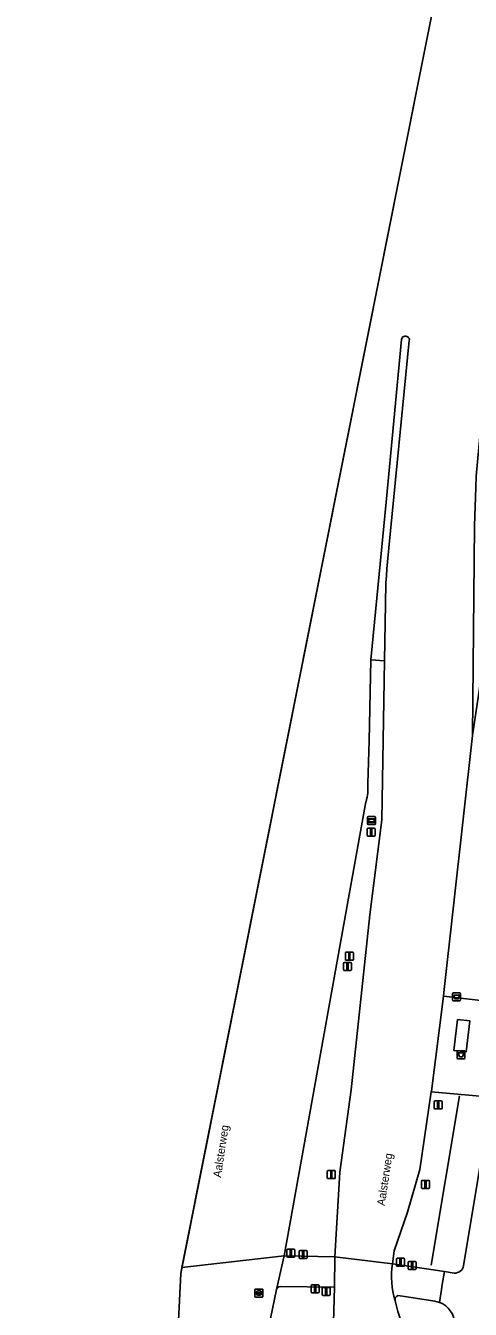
# Model space of a CAD drawing. Extents: x 161483 to 162250, y 379484 to 380833.
# Drawn here: x 161483 to 161538.6, y 379648 to 379808.4 of the extents above; entities that cross this region are included whole.
import ezdxf

# ---------------------------------------------------------------- set-up
doc = ezdxf.new("R2010")
doc.units = 0
for name, color, linetype in [('IMGEO_Afvalbak', 7, 'Continuous'), ('IMGEO_Berm_groen', 7, 'Continuous'), ('IMGEO_Drukknoppaal', 7, 'Continuous'), ('IMGEO_Fietspad_open', 7, 'Continuous'), ('IMGEO_Hek', 7, 'Continuous'), ('IMGEO_Lichtmast', 7, 'Continuous'), ('IMGEO_Openbare_ruimte_label', 7, 'Continuous'), ('IMGEO_Rijbaan_lokaal_open', 7, 'Continuous'), ('IMGEO_Rijbaan_regionaal_gesloten', 7, 'Continuous'), ('IMGEO_Rioolput', 7, 'Continuous'), ('IMGEO_Verkeersbordpaal', 7, 'Continuous'), ('IMGEO_Verkeerseiland_groen', 7, 'Continuous'), ('IMGEO_Verkeerseiland_open', 7, 'Continuous'), ('IMGEO_Verkeersregelinstallatiepaal', 7, 'Continuous'), ('IMGEO_Voetpad_open', 7, 'Continuous'), ('IMGEO_Wegwijzer', 7, 'Continuous')]:
    doc.layers.add(name, color=color, linetype=linetype)

msp = doc.modelspace()

# ---------------------------------------------------------------- linework, layer by layer
at = {"layer": 'IMGEO_Afvalbak'}
for p, q in [((161536.37, 379686.67), (161536.37, 379687.47)), ((161536.37, 379687.47), (161536.37, 379686.67)), ((161536.47, 379687.57), (161537.26, 379687.57)), ((161537.26, 379687.57), (161536.47, 379687.57)), ((161537.36, 379687.47), (161537.36, 379686.67)), ((161537.36, 379686.67), (161537.36, 379687.47)), ((161537.26, 379686.57), (161536.47, 379686.57)), ((161536.47, 379686.57), (161537.26, 379686.57)), ((161536.92, 379679.45), (161536.92, 379680.25)), ((161536.92, 379680.25), (161536.92, 379679.45)), ((161537.02, 379680.35), (161537.81, 379680.35)), ((161537.81, 379680.35), (161537.02, 379680.35)), ((161537.91, 379680.25), (161537.91, 379679.45)), ((161537.91, 379679.45), (161537.91, 379680.25)), ((161537.81, 379679.35), (161537.02, 379679.35)), ((161537.02, 379679.35), (161537.81, 379679.35))]:
    msp.add_line(p, q, dxfattribs=at)
for points in [[(161536.51, 379687.28), (161537.22, 379687.28), (161537.07, 379686.81), (161536.66, 379686.81), (161536.51, 379687.28)], [(161537.06, 379680.07), (161537.76, 379680.07), (161537.61, 379679.6), (161537.21, 379679.6), (161537.06, 379680.07)]]:
    msp.add_lwpolyline(points, dxfattribs=at)
for centre, start, end in [((161536.47, 379687.47), 90, 180), ((161536.47, 379687.47), 90, 180), ((161536.47, 379686.67), 180, 270), ((161536.47, 379686.67), 180, 270), ((161537.26, 379687.47), 0, 90), ((161537.26, 379687.47), 360, 90), ((161537.26, 379686.67), 270, 0), ((161537.26, 379686.67), 270, 0), ((161537.02, 379680.25), 90, 180), ((161537.02, 379680.25), 90, 180), ((161537.81, 379680.25), 0, 90), ((161537.81, 379680.25), 360, 90), ((161537.02, 379679.45), 180, 270), ((161537.02, 379679.45), 180, 270), ((161537.81, 379679.45), 270, 0), ((161537.81, 379679.45), 270, 0)]:
    msp.add_arc(centre, 0.1, start, end, dxfattribs=at)
at = {"layer": 'IMGEO_Berm_groen'}
msp.add_lwpolyline([(161542.27, 379719.34), (161542.78, 379730.23), (161541.86, 379730.38), (161541.18, 379730.51), (161540.46, 379730.63), (161538.85, 379719.7), (161535.27, 379687.62), (161535.21, 379687.18), (161540.62, 379686.53), (161541.04, 379686.2)], close=True, dxfattribs=at)
for points in [[(161522.29, 379665.17), (161523.69, 379675.46), (161526.05, 379697.32), (161527.54, 379709.18), (161527.86, 379729.05), (161526.15, 379729.17), (161525.94, 379719.07), (161525.77, 379713.72)], [(161525.55, 379711.44), (161515.33, 379654.71), (161521.67, 379654.59), (161522.29, 379665.17)], [(161541.25, 379674.78), (161540.83, 379674.58), (161540.26, 379674.63), (161533.71, 379675.2), (161532.29, 379665.51), (161530.75, 379660.18), (161529.05, 379655.33), (161528.86, 379653.72), (161535.35, 379652.76), (161536.58, 379652.57)], [(161537.74, 379653.47), (161541.25, 379674.78)]]:
    msp.add_lwpolyline(points, dxfattribs=at)
for centre, radius, start, end in [((161518.89, 379713.22), 6.9, 345.0367, 4.1254), ((161536.63, 379653.71), 1.14, 267.5903, 347.9888)]:
    msp.add_arc(centre, radius, start, end, dxfattribs=at)
at = {"layer": 'IMGEO_Drukknoppaal'}
for p, q in [((161517.21, 379654.49), (161517.21, 379655.28)), ((161517.21, 379655.28), (161517.21, 379654.49)), ((161517.31, 379655.38), (161518.1, 379655.38)), ((161518.1, 379655.38), (161517.31, 379655.38)), ((161518.2, 379655.28), (161518.2, 379654.49)), ((161518.2, 379654.49), (161518.2, 379655.28)), ((161518.1, 379654.39), (161517.31, 379654.39)), ((161517.31, 379654.39), (161518.1, 379654.39)), ((161530.82, 379653.12), (161530.82, 379653.92)), ((161530.82, 379653.92), (161530.82, 379653.12)), ((161530.92, 379654.02), (161531.71, 379654.02)), ((161531.71, 379654.02), (161530.92, 379654.02)), ((161531.71, 379653.02), (161530.92, 379653.02)), ((161530.92, 379653.02), (161531.71, 379653.02)), ((161531.81, 379653.92), (161531.81, 379653.12)), ((161531.81, 379653.12), (161531.81, 379653.92)), ((161518.71, 379650.21), (161518.71, 379651)), ((161518.71, 379651), (161518.71, 379650.21)), ((161518.81, 379651.1), (161519.6, 379651.1)), ((161519.6, 379651.1), (161518.81, 379651.1)), ((161519.6, 379650.11), (161518.81, 379650.11)), ((161518.81, 379650.11), (161519.6, 379650.11)), ((161519.7, 379651), (161519.7, 379650.21)), ((161519.7, 379650.21), (161519.7, 379651))]:
    msp.add_line(p, q, dxfattribs=at)
for points in [[(161517.63, 379655.26), (161517.78, 379655.26), (161517.78, 379654.51), (161517.63, 379654.51), (161517.63, 379655.26)], [(161531.24, 379653.9), (161531.39, 379653.9), (161531.39, 379653.15), (161531.24, 379653.15), (161531.24, 379653.9)], [(161519.13, 379650.98), (161519.28, 379650.98), (161519.28, 379650.23), (161519.13, 379650.23), (161519.13, 379650.98)]]:
    msp.add_lwpolyline(points, dxfattribs=at)
for centre, start, end in [((161517.31, 379655.28), 90, 180), ((161517.31, 379655.28), 90, 180), ((161518.1, 379655.28), 0, 90), ((161518.1, 379655.28), 360, 90), ((161517.31, 379654.49), 180, 270), ((161517.31, 379654.49), 180, 270), ((161518.1, 379654.49), 270, 0), ((161518.1, 379654.49), 270, 0), ((161530.92, 379653.92), 90, 180), ((161530.92, 379653.92), 90, 180), ((161530.92, 379653.12), 180, 270), ((161530.92, 379653.12), 180, 270), ((161531.71, 379653.92), 0, 90), ((161531.71, 379653.92), 360, 90), ((161531.71, 379653.12), 270, 0), ((161531.71, 379653.12), 270, 0), ((161518.81, 379651), 90, 180), ((161518.81, 379651), 90, 180), ((161518.81, 379650.21), 180, 270), ((161518.81, 379650.21), 180, 270), ((161519.6, 379651), 0, 90), ((161519.6, 379651), 360, 90), ((161519.6, 379650.21), 270, 0), ((161519.6, 379650.21), 270, 0)]:
    msp.add_arc(centre, 0.1, start, end, dxfattribs=at)
at = {"layer": 'IMGEO_Fietspad_open'}
for points in [[(161514.82, 379650.91), (161521.6, 379650.81), (161521.67, 379654.59), (161515.33, 379654.71), (161514.37, 379650.53)], [(161529.57, 379649.77), (161534.16, 379649.05), (161534.75, 379648.9), (161534.98, 379650.53), (161535.08, 379651.14), (161535.35, 379652.76), (161528.86, 379653.72)]]:
    msp.add_lwpolyline(points, dxfattribs=at)
for centre, radius, start, end in [((161539.2, 379652.17), 10.46, 171.4979, 196.8847), ((161514.87, 379650.4), 0.512, 95.2688, 165.5121), ((161529.68, 379649.27), 0.505, 102.4354, 196.3818)]:
    msp.add_arc(centre, radius, start, end, dxfattribs=at)
at = {"layer": 'IMGEO_Hek'}
msp.add_lwpolyline([(161533.7, 379653.57), (161537.24, 379674.7)], dxfattribs=at)
at = {"layer": 'IMGEO_Lichtmast'}
for p, q in [((161534.07, 379673.17), (161534.07, 379673.97)), ((161534.07, 379673.97), (161534.07, 379673.17)), ((161534.17, 379674.07), (161534.96, 379674.07)), ((161534.96, 379674.07), (161534.17, 379674.07)), ((161535.06, 379673.97), (161535.06, 379673.17)), ((161535.06, 379673.17), (161535.06, 379673.97)), ((161534.96, 379673.07), (161534.17, 379673.07)), ((161534.17, 379673.07), (161534.96, 379673.07))]:
    msp.add_line(p, q, dxfattribs=at)
msp.add_lwpolyline([(161534.49, 379673.94), (161534.64, 379673.94), (161534.64, 379673.19), (161534.49, 379673.19), (161534.49, 379673.94)], dxfattribs=at)
for centre, start, end in [((161534.17, 379673.97), 90, 180), ((161534.17, 379673.97), 90, 180), ((161534.96, 379673.97), 0, 90), ((161534.96, 379673.97), 360, 90), ((161534.17, 379673.17), 180, 270), ((161534.17, 379673.17), 180, 270), ((161534.96, 379673.17), 270, 0), ((161534.96, 379673.17), 270, 0)]:
    msp.add_arc(centre, 0.1, start, end, dxfattribs=at)
at = {"layer": 'IMGEO_Rijbaan_lokaal_open'}
for points in [[(161568.67, 379924.98), (161568.64, 379924.71), (161566.42, 379910.1), (161555.39, 379837.58), (161553.58, 379825.73), (161553.13, 379822.77), (161553.05, 379822.24), (161552.68, 379819.89), (161552.15, 379816.61), (161551.31, 379810.23), (161550.68, 379806.2), (161549.37, 379797.47), (161545.28, 379765.99), (161545.09, 379763.98), (161543.3, 379741.06), (161542.78, 379730.23), (161542.27, 379719.34), (161541.04, 379686.2), (161541.25, 379674.78), (161537.74, 379653.47)], [(161536.58, 379652.57), (161535.35, 379652.76), (161535.08, 379651.14), (161534.98, 379650.53), (161534.75, 379648.9)]]:
    msp.add_lwpolyline(points, dxfattribs=at)
for centre, radius, start, end in [((161536.63, 379653.71), 1.14, 267.5903, 347.9888), ((161533.72, 379646.19), 2.9, 1.8343, 69.0793)]:
    msp.add_arc(centre, radius, start, end, dxfattribs=at)
at = {"layer": 'IMGEO_Rijbaan_regionaal_gesloten'}
for points in [[(161637.54, 380449.19), (161634.42, 380428.72), (161633.8, 380424.68), (161622.13, 380350.53), (161608.3, 380261.7), (161590.69, 380150.92), (161580.24, 380085.17), (161544.18, 379852.27), (161534.04, 379811.02), (161532.83, 379804.99), (161502.42, 379652.5), (161501.18, 379627.2), (161487.61, 379545.27), (161483.05, 379509.29), (161486.22, 379508.49)], [(161637.54, 380449.19), (161634.42, 380428.72), (161633.8, 380424.68), (161622.13, 380350.53), (161608.3, 380261.7), (161590.69, 380150.92), (161580.24, 380085.17), (161544.18, 379852.27), (161534.04, 379811.02), (161532.83, 379804.99), (161502.57, 379653.26), (161515.33, 379654.71), (161525.55, 379711.44)], [(161528.86, 379653.72), (161529.05, 379655.33), (161530.75, 379660.18), (161532.29, 379665.51), (161533.71, 379675.2), (161533.73, 379675.3), (161535.21, 379687.18), (161535.27, 379687.62), (161538.85, 379719.7), (161539.12, 379745.9), (161539.25, 379750.7), (161539.33, 379752.11), (161540.11, 379760.61), (161541.48, 379775.69), (161542.99, 379790.84), (161543.9, 379799.22), (161544.15, 379801.55), (161544.17, 379801.74), (161544.23, 379802.25), (161545.48, 379814.72)], [(161525.77, 379713.72), (161525.94, 379719.07), (161526.15, 379729.17), (161528.05, 379748.88), (161529.97, 379769.17)], [(161525.77, 379713.72), (161525.94, 379719.07), (161526.15, 379729.17), (161528.05, 379748.88), (161529.97, 379769.17)], [(161530.96, 379769.04), (161528.4, 379743.14)], [(161530.96, 379769.04), (161528.4, 379743.14)], [(161527.99, 379736.15), (161527.86, 379729.05), (161527.54, 379709.18), (161526.05, 379697.32), (161523.69, 379675.46), (161522.29, 379665.17), (161521.67, 379654.59), (161521.6, 379650.81), (161521.4, 379643.48), (161521.05, 379638.92), (161520.9, 379637.5)], [(161527.99, 379736.15), (161527.86, 379729.05), (161527.54, 379709.18), (161526.05, 379697.32), (161523.69, 379675.46), (161522.29, 379665.17), (161521.67, 379654.59), (161528.86, 379653.72), (161529.05, 379655.33), (161530.75, 379660.18), (161532.29, 379665.51), (161533.71, 379675.2), (161533.73, 379675.3), (161535.21, 379687.18), (161535.27, 379687.62), (161538.85, 379719.7)], [(161511.86, 379638.41), (161512.11, 379639.67), (161514.37, 379650.53), (161515.33, 379654.71), (161525.55, 379711.44)], [(161511.86, 379638.41), (161512.11, 379639.67), (161514.37, 379650.53), (161515.33, 379654.71), (161502.57, 379653.26), (161502.42, 379652.5), (161501.18, 379627.2), (161487.61, 379545.27), (161483.05, 379509.29), (161486.22, 379508.49)], [(161528.86, 379653.72), (161521.67, 379654.59), (161521.6, 379650.81), (161521.4, 379643.48), (161521.05, 379638.92), (161520.9, 379637.5)]]:
    msp.add_lwpolyline(points, dxfattribs=at)
for centre, radius, start, end in [((161530.47, 379769.11), 0.496, 351.0183, 173.2277), ((161530.47, 379769.11), 0.496, 351.0183, 173.2277), ((161589.48, 379736.11), 61.49, 173.4364, 179.9595), ((161589.48, 379736.11), 61.49, 173.4364, 179.9595), ((161518.89, 379713.22), 6.9, 345.0367, 4.1254), ((161518.89, 379713.22), 6.9, 345.0367, 4.1254), ((161539.2, 379652.17), 10.46, 171.4979, 196.8847), ((161539.2, 379652.17), 10.46, 171.4979, 196.8847), ((161544.53, 379652.12), 15.62, 191.0122, 231.4287), ((161544.53, 379652.12), 15.62, 191.0122, 231.4287)]:
    msp.add_arc(centre, radius, start, end, dxfattribs=at)
at = {"layer": 'IMGEO_Rioolput'}
for p, q in [((161511.68, 379649.65), (161511.68, 379650.5)), ((161511.76, 379650.58), (161512.61, 379650.58)), ((161511.94, 379650.07), (161511.94, 379650.08)), ((161511.98, 379650.12), (161512.38, 379650.12)), ((161512.38, 379650.03), (161511.98, 379650.03)), ((161512.17, 379650.36), (161512.2, 379650.36)), ((161512.19, 379649.8), (161512.17, 379649.8)), ((161512.43, 379650.08), (161512.43, 379650.07)), ((161512.68, 379650.5), (161512.68, 379649.65)), ((161512.61, 379649.58), (161511.76, 379649.58))]:
    msp.add_line(p, q, dxfattribs=at)
for points in [[(161511.68, 379649.65), (161511.68, 379650.5)], [(161511.76, 379650.58), (161512.61, 379650.58)], [(161512.68, 379650.5), (161512.68, 379649.65)], [(161512.61, 379649.58), (161511.76, 379649.58)]]:
    msp.add_lwpolyline(points, dxfattribs=at)
for centre, radius, start, end in [((161511.76, 379650.5), 0.0765, 91.552, 178.448), ((161511.76, 379650.5), 0.0765, 91.552, 178.448), ((161511.98, 379650.08), 0.0403, 85.8775, 175.7526), ((161511.98, 379650.07), 0.0366, 178.938, 274.7102), ((161512.39, 379650.08), 0.0386, 1.7309, 96.639), ((161512.38, 379650.08), 0.043, 264.8664, 352.4533), ((161512.61, 379650.5), 0.0765, 1.552, 88.448), ((161512.61, 379650.5), 0.0765, 1.552, 88.448), ((161511.76, 379649.65), 0.0765, 181.552, 268.448), ((161511.76, 379649.65), 0.0765, 181.552, 268.448), ((161512.61, 379649.65), 0.0765, 271.552, 358.448), ((161512.61, 379649.65), 0.0765, 271.552, 358.448)]:
    msp.add_arc(centre, radius, start, end, dxfattribs=at)
for centre, major_axis, ratio, start_param, end_param in [((161512.17, 379650.08), (-0.387, 0.002), 0.722429, 4.712389, 7.853982), ((161512.19, 379650.08), (-0.39, 0.002), 0.717154, 1.570796, 4.712389)]:
    msp.add_ellipse(centre, major_axis=major_axis, ratio=ratio, start_param=start_param, end_param=end_param, dxfattribs=at)
at = {"layer": 'IMGEO_Verkeersbordpaal'}
for p, q in [((161525.7, 379707.24), (161525.7, 379708.04)), ((161525.7, 379708.04), (161525.7, 379707.24)), ((161525.8, 379708.14), (161526.58, 379708.14)), ((161526.58, 379708.14), (161525.8, 379708.14)), ((161526.68, 379708.04), (161526.68, 379707.24)), ((161526.68, 379707.24), (161526.68, 379708.04)), ((161526.58, 379707.14), (161525.8, 379707.14)), ((161525.8, 379707.14), (161526.58, 379707.14)), ((161522.98, 379691.74), (161522.98, 379692.54)), ((161522.98, 379692.54), (161522.98, 379691.74)), ((161523.08, 379692.64), (161523.87, 379692.64)), ((161523.87, 379692.64), (161523.08, 379692.64)), ((161523.87, 379691.64), (161523.08, 379691.64)), ((161523.08, 379691.64), (161523.87, 379691.64)), ((161523.97, 379692.54), (161523.97, 379691.74)), ((161523.97, 379691.74), (161523.97, 379692.54)), ((161522.74, 379690.46), (161522.74, 379691.26)), ((161522.74, 379691.26), (161522.74, 379690.46)), ((161522.84, 379691.36), (161523.63, 379691.36)), ((161523.63, 379691.36), (161522.84, 379691.36)), ((161523.63, 379690.36), (161522.84, 379690.36)), ((161522.84, 379690.36), (161523.63, 379690.36)), ((161523.73, 379691.26), (161523.73, 379690.46)), ((161523.73, 379690.46), (161523.73, 379691.26)), ((161520.72, 379664.47), (161520.72, 379665.27)), ((161520.72, 379665.27), (161520.72, 379664.47)), ((161520.82, 379665.37), (161521.61, 379665.37)), ((161521.61, 379665.37), (161520.82, 379665.37)), ((161521.61, 379664.37), (161520.82, 379664.37)), ((161520.82, 379664.37), (161521.61, 379664.37)), ((161521.71, 379665.27), (161521.71, 379664.47)), ((161521.71, 379664.47), (161521.71, 379665.27)), ((161532.48, 379663.25), (161532.48, 379664.05)), ((161532.48, 379664.05), (161532.48, 379663.25)), ((161532.58, 379664.15), (161533.37, 379664.15)), ((161533.37, 379664.15), (161532.58, 379664.15)), ((161533.37, 379663.15), (161532.58, 379663.15)), ((161532.58, 379663.15), (161533.37, 379663.15)), ((161533.47, 379664.05), (161533.47, 379663.25)), ((161533.47, 379663.25), (161533.47, 379664.05))]:
    msp.add_line(p, q, dxfattribs=at)
for points in [[(161526.11, 379708.02), (161526.27, 379708.02), (161526.27, 379707.27), (161526.11, 379707.27), (161526.11, 379708.02)], [(161523.4, 379692.52), (161523.55, 379692.52), (161523.55, 379691.77), (161523.4, 379691.77), (161523.4, 379692.52)], [(161523.16, 379691.23), (161523.31, 379691.23), (161523.31, 379690.48), (161523.16, 379690.48), (161523.16, 379691.23)], [(161521.14, 379665.24), (161521.29, 379665.24), (161521.29, 379664.49), (161521.14, 379664.49), (161521.14, 379665.24)], [(161532.9, 379664.03), (161533.05, 379664.03), (161533.05, 379663.28), (161532.9, 379663.28), (161532.9, 379664.03)]]:
    msp.add_lwpolyline(points, dxfattribs=at)
for centre, start, end in [((161525.8, 379708.04), 90, 180), ((161525.8, 379708.04), 90, 180), ((161526.58, 379708.04), 0, 90), ((161526.58, 379708.04), 360, 90), ((161525.8, 379707.24), 180, 270), ((161525.8, 379707.24), 180, 270), ((161526.58, 379707.24), 270, 0), ((161526.58, 379707.24), 270, 0), ((161523.08, 379692.54), 90, 180), ((161523.08, 379692.54), 90, 180), ((161523.08, 379691.74), 180, 270), ((161523.08, 379691.74), 180, 270), ((161523.87, 379692.54), 0, 90), ((161523.87, 379692.54), 360, 90), ((161523.87, 379691.74), 270, 0), ((161523.87, 379691.74), 270, 0), ((161522.84, 379691.26), 90, 180), ((161522.84, 379691.26), 90, 180), ((161522.84, 379690.46), 180, 270), ((161522.84, 379690.46), 180, 270), ((161523.63, 379691.26), 0, 90), ((161523.63, 379691.26), 360, 90), ((161523.63, 379690.46), 270, 0), ((161523.63, 379690.46), 270, 0), ((161520.82, 379665.27), 90, 180), ((161520.82, 379665.27), 90, 180), ((161520.82, 379664.47), 180, 270), ((161520.82, 379664.47), 180, 270), ((161521.61, 379665.27), 0, 90), ((161521.61, 379665.27), 360, 90), ((161521.61, 379664.47), 270, 0), ((161521.61, 379664.47), 270, 0), ((161532.58, 379664.05), 90, 180), ((161532.58, 379664.05), 90, 180), ((161532.58, 379663.25), 180, 270), ((161532.58, 379663.25), 180, 270), ((161533.37, 379664.05), 0, 90), ((161533.37, 379664.05), 360, 90), ((161533.37, 379663.25), 270, 0), ((161533.37, 379663.25), 270, 0)]:
    msp.add_arc(centre, 0.1, start, end, dxfattribs=at)
at = {"layer": 'IMGEO_Verkeerseiland_groen'}
for points in [[(161514.37, 379650.53), (161512.11, 379639.67), (161521.05, 379638.92), (161521.4, 379643.48), (161521.6, 379650.81)], [(161521.6, 379650.81), (161514.82, 379650.91)], [(161534.75, 379648.9), (161534.16, 379649.05), (161529.57, 379649.77)]]:
    msp.add_lwpolyline(points, dxfattribs=at)
for centre, radius, start, end in [((161514.87, 379650.4), 0.512, 95.2688, 165.5121), ((161529.68, 379649.27), 0.505, 102.4354, 196.3818), ((161544.53, 379652.12), 15.62, 191.0122, 231.4287), ((161533.72, 379646.19), 2.9, 1.8343, 69.0793)]:
    msp.add_arc(centre, radius, start, end, dxfattribs=at)
at = {"layer": 'IMGEO_Verkeerseiland_open'}
for points in [[(161529.97, 379769.17), (161528.05, 379748.88), (161526.15, 379729.17), (161527.86, 379729.05), (161527.99, 379736.15)], [(161528.4, 379743.14), (161530.96, 379769.04)]]:
    msp.add_lwpolyline(points, dxfattribs=at)
for centre, radius, start, end in [((161530.47, 379769.11), 0.496, 351.0183, 173.2277), ((161589.48, 379736.11), 61.49, 173.4364, 179.9595)]:
    msp.add_arc(centre, radius, start, end, dxfattribs=at)
at = {"layer": 'IMGEO_Verkeersregelinstallatiepaal'}
for p, q in [((161515.68, 379654.67), (161515.68, 379655.46)), ((161515.68, 379655.46), (161515.68, 379654.67)), ((161515.78, 379655.56), (161516.57, 379655.56)), ((161516.57, 379655.56), (161515.78, 379655.56)), ((161516.57, 379654.57), (161515.78, 379654.57)), ((161515.78, 379654.57), (161516.57, 379654.57)), ((161516.67, 379655.46), (161516.67, 379654.67)), ((161516.67, 379654.67), (161516.67, 379655.46)), ((161529.36, 379653.52), (161529.36, 379654.32)), ((161529.36, 379654.32), (161529.36, 379653.52)), ((161529.46, 379654.42), (161530.25, 379654.42)), ((161530.25, 379654.42), (161529.46, 379654.42)), ((161530.25, 379653.42), (161529.46, 379653.42)), ((161529.46, 379653.42), (161530.25, 379653.42)), ((161530.35, 379654.32), (161530.35, 379653.52)), ((161530.35, 379653.52), (161530.35, 379654.32)), ((161520.07, 379649.89), (161520.07, 379650.69)), ((161520.07, 379650.69), (161520.07, 379649.89)), ((161520.17, 379650.79), (161520.96, 379650.79)), ((161520.96, 379650.79), (161520.17, 379650.79)), ((161520.96, 379649.79), (161520.17, 379649.79)), ((161520.17, 379649.79), (161520.96, 379649.79)), ((161521.06, 379650.69), (161521.06, 379649.89)), ((161521.06, 379649.89), (161521.06, 379650.69))]:
    msp.add_line(p, q, dxfattribs=at)
for points in [[(161516.1, 379655.44), (161516.25, 379655.44), (161516.25, 379654.69), (161516.1, 379654.69), (161516.1, 379655.44)], [(161529.78, 379654.3), (161529.93, 379654.3), (161529.93, 379653.55), (161529.78, 379653.55), (161529.78, 379654.3)], [(161520.49, 379650.66), (161520.64, 379650.66), (161520.64, 379649.91), (161520.49, 379649.91), (161520.49, 379650.66)]]:
    msp.add_lwpolyline(points, dxfattribs=at)
for centre, start, end in [((161515.78, 379655.46), 90, 180), ((161515.78, 379655.46), 90, 180), ((161515.78, 379654.67), 180, 270), ((161515.78, 379654.67), 180, 270), ((161516.57, 379655.46), 0, 90), ((161516.57, 379655.46), 360, 90), ((161516.57, 379654.67), 270, 0), ((161516.57, 379654.67), 270, 0), ((161529.46, 379654.32), 90, 180), ((161529.46, 379654.32), 90, 180), ((161529.46, 379653.52), 180, 270), ((161529.46, 379653.52), 180, 270), ((161530.25, 379654.32), 0, 90), ((161530.25, 379654.32), 360, 90), ((161530.25, 379653.52), 270, 0), ((161530.25, 379653.52), 270, 0), ((161520.17, 379650.69), 90, 180), ((161520.17, 379650.69), 90, 180), ((161520.17, 379649.89), 180, 270), ((161520.17, 379649.89), 180, 270), ((161520.96, 379650.69), 0, 90), ((161520.96, 379650.69), 360, 90), ((161520.96, 379649.89), 270, 0), ((161520.96, 379649.89), 270, 0)]:
    msp.add_arc(centre, 0.1, start, end, dxfattribs=at)
at = {"layer": 'IMGEO_Voetpad_open'}
for points in [[(161541.04, 379686.2), (161540.62, 379686.53), (161535.21, 379687.18), (161533.73, 379675.3), (161533.71, 379675.2), (161540.26, 379674.63), (161540.83, 379674.58), (161541.25, 379674.78)], [(161538.52, 379684.06), (161536.99, 379684.24), (161536.54, 379680.37), (161538.06, 379680.19)], [(161536.54, 379680.37), (161536.99, 379684.24), (161538.52, 379684.06), (161538.06, 379680.19)]]:
    msp.add_lwpolyline(points, close=True, dxfattribs=at)
at = {"layer": 'IMGEO_Wegwijzer'}
for p, q in [((161525.74, 379708.69), (161525.74, 379709.49)), ((161525.74, 379709.49), (161525.74, 379708.69)), ((161525.84, 379709.59), (161526.62, 379709.59)), ((161526.62, 379709.59), (161525.84, 379709.59)), ((161526.72, 379709.49), (161526.72, 379708.69)), ((161526.72, 379708.69), (161526.72, 379709.49)), ((161526.62, 379708.59), (161525.84, 379708.59)), ((161525.84, 379708.59), (161526.62, 379708.59))]:
    msp.add_line(p, q, dxfattribs=at)
for points in [[(161525.84, 379709.33), (161526.62, 379709.33), (161526.62, 379708.86), (161525.84, 379708.86), (161525.84, 379709.33)], [(161525.9, 379709.26), (161525.9, 379708.93), (161526.56, 379708.93), (161526.56, 379709.26), (161525.9, 379709.26)]]:
    msp.add_lwpolyline(points, dxfattribs=at)
for centre, start, end in [((161525.84, 379709.49), 90, 180), ((161525.84, 379709.49), 90, 180), ((161526.62, 379709.49), 0, 90), ((161526.62, 379709.49), 360, 90), ((161525.84, 379708.69), 180, 270), ((161525.84, 379708.69), 180, 270), ((161526.62, 379708.69), 270, 0), ((161526.62, 379708.69), 270, 0)]:
    msp.add_arc(centre, 0.1, start, end, dxfattribs=at)

# ---------------------------------------------------------------- texts
at = {"layer": 'IMGEO_Openbare_ruimte_label'}
for p in [(161507.43, 379664.45), (161527.89, 379660.93)]:
    msp.add_text('Aalsterweg', height=1, rotation=81.4324, dxfattribs=at).set_placement(p)

doc.saveas('drawing.dxf')
